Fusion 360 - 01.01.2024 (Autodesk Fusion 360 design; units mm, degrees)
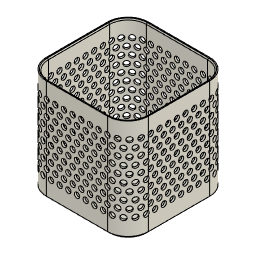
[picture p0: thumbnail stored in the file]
parameter "width" = 100
parameter "length" = 100
parameter "height" = 100
parameter "wall" = 2
parameter "hole_diameter" = 5.2
parameter "corner_radius" = 20
parameter "hole_wall" = 3.2
parameter "hole_vertical_distance" = 7.3645 (= "hole_horizontal_distance * sin(60 deg)")
parameter "hole_savespace" = 10
sketch "Skizze1" plane through (0, 0, 0) normal (0, 0, 1) x axis (1, 0, 0)
  line L1 (-30, 50) -> (30, 50)
  line L2 (-50, -30) -> (-50, 30)
  line L3 (30, -50) -> (-30, -50)
  line L4 (50, 30) -> (50, -30)
  line L5 (-50, -50) -> (50, 50)
  line L6 (50, -50) -> (-50, 50)
  arc A1 centre (-30, 30) radius 20 clockwise from (-50, 30) to (-30, 50)
  arc A2 centre (30, 30) radius 20 clockwise from (30, 50) to (50, 30)
  arc A3 centre (30, -30) radius 20 clockwise from (50, -30) to (30, -50)
  arc A4 centre (-30, -30) radius 20 clockwise from (-30, -50) to (-50, -30)
  point P6 (0, 0)
  point P1 (0, 0)
  point P3 (-50, 50)
  point P2 (50, 50)
  point P5 (50, -50)
  point P4 (-50, -50)
  horizontal L1
  perpendicular L1 L2
  parallel L1 L3
  parallel L2 L4
  coincident L5 P6
  coincident L6 P6
  coincident P1 P6
  coincident P3 L2
  coincident P3 L1
  tangent L2 A1
  tangent L1 A1
  coincident P2 L1
  coincident P2 L4
  tangent L1 A2
  tangent L4 A2
  coincident P5 L4
  coincident P5 L3
  tangent L4 A3
  tangent L3 A3
  coincident P4 L3
  coincident P4 L2
  tangent L3 A4
  tangent L2 A4
  dimension "d1" distance P4 P5 = 100 (= "width")
  dimension "d2" distance P3 P4 = 100 (= "length")
  dimension "d3" radius A1 = 20 (= "corner_radius")
  dimension "d4" radius A2 = 20 (= "corner_radius")
  dimension "d5" radius A3 = 20 (= "corner_radius")
  dimension "d6" radius A4 = 20 (= "corner_radius")
extrude "Extrusion1" new body sketch "Skizze1" profile of L1 L2 L3 L4 A1 A2 A3 A4 along normal blind 2 (= "wall") bodies "Box"
extrude "Extrusion2" new body blind 98 (= "height - wall") from offset 2 (= "wall") Side1WallThickness 2 (= "wall")
sketch "Skizze2" plane through (0, -50, 0) normal (0, -1, 0) x axis (1, 0, 0)
  line L1 (30, 2) -> (-30, 2)
  line L2 (30, 100) -> (30, 2)
  line L3 (-30, 100) -> (30, 100)
  line L4 (-30, 2) -> (-30, 100)
  line L5 (4.2519, 25.2242) -> (-4.2519, 25.2242)
  line L6 (0, 17.8597) -> (4.2519, 25.2242)
  line L7 (-4.2519, 25.2242) -> (0, 17.8597)
  line L8 (0, 2) -> (0, 100)
  circle C1 centre (4.2519, 25.2242) radius 2.6
  circle C2 centre (-4.2519, 25.2242) radius 2.6
  circle C3 centre (0, 17.8597) radius 2.6
  point P7 (0, 100)
  point P2 (4.2519, 25.2242)
  point P9 (-4.2519, 25.2242)
  point P11 (-4.2519, 25.2242)
  point P12 (4.2519, 25.2242)
  point P10 (0, 17.8597)
  point P13 (0, 17.8597)
  point P14 (0, 15.2597)
  point P15 (0, 100)
  point P16 (0, 2)
  midpoint L3 P7
  horizontal P2 P9
  coincident P9 P11
  coincident P2 P12
  coincident P10 P13
  coincident C3 P14
  coincident P7 P15
  midpoint L1 P16
  coincident P10 L8
  coincident P14 L8
  dimension "d15" diameter C1 = 5.2 (= "hole_diameter")
  dimension "d58" diameter C2 = 5.2 (= "hole_diameter")
  dimension "d60" diameter C3 = 5.2 (= "hole_diameter")
  dimension "d62" distance P9 P10 = 8.5038 (= "hole_horizontal_distance")
  dimension "d82" distance P2 P9 = 8.5038 (= "hole_horizontal_distance")
  dimension "d83" distance P2 P10 = 8.5038 (= "hole_horizontal_distance")
  dimension "d106" distance L1 P14 = 13.2597 (= "hole_start")
extrude "Extrusion4" cut sketch "Skizze2" profile of C3 against normal blind 4 (magnitude of "-wall * 2")
path_pattern "Pfadanordnung2" sketch "Skizze2" PathPatternDelta 8.5038 (= "hole_horizontal_distance")
extrude "Extrusion3" cut sketch "Skizze2" profile of C1 against normal blind 4 (magnitude of "-wall * 2")
path_pattern "Pfadanordnung1" PathPatternDelta 8.5038 (= "hole_horizontal_distance")
rectangular_pattern "R-Anordnung4" countU 5 (= "hole_vertical_variant_1_count") uSpaceDistance 14.729 (= "hole_vertical_distance * 2") vSpaceDistance 0
rectangular_pattern "R-Anordnung5" countU 5 (= "hole_vertical_variant_2_count") uSpaceDistance 14.729 (= "hole_vertical_distance * 2") vSpaceDistance 0
combine "Kombinieren"
chamfer "Fase" distance 1 (= "wall / 2") distance 2 (= "wall")
named bodies: "Box"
